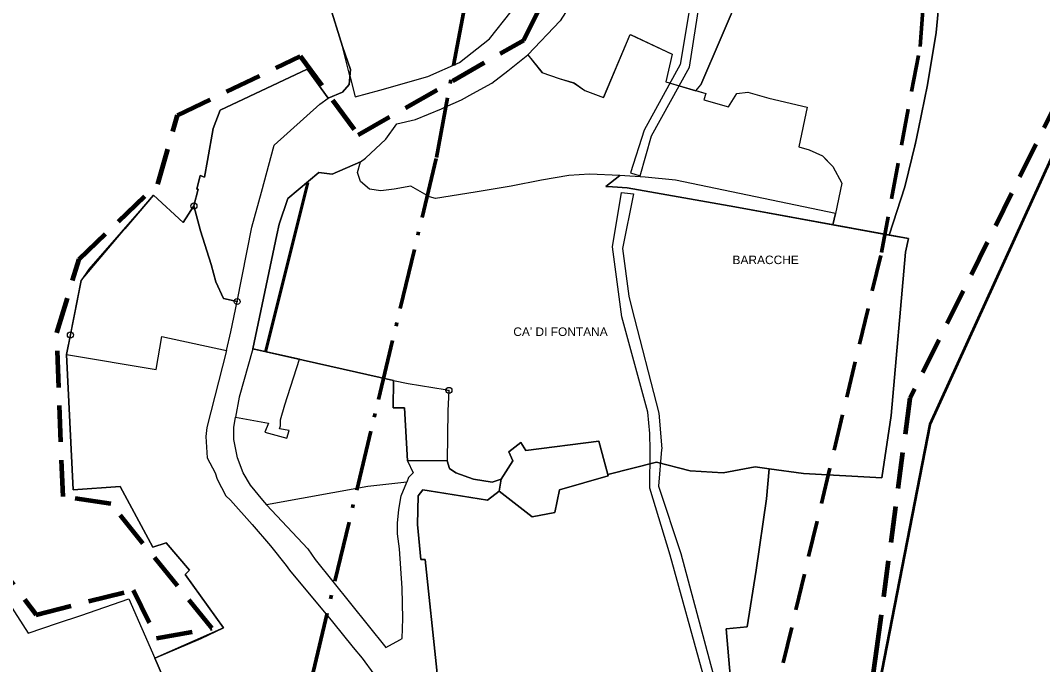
# Model space of a CAD drawing. Extents: x 654952 to 658955, y 890426 to 894481.
# Drawn here: x 657975.8 to 658312.8, y 893012.3 to 893224.6 of the extents above; entities that cross this region are included whole.
import ezdxf

# ---------------------------------------------------------------- set-up
doc = ezdxf.new("R2010")
doc.units = 0
doc.header["$LTSCALE"] = 4
doc.header["$PDMODE"] = 32
doc.header["$PDSIZE"] = 2
doc.linetypes.add('DOT_DASHED', pattern=[7.7, 5, -1.2, 0.3, -1.2])
doc.linetypes.add('MEDIUM_DASHED', pattern=[4.5, 3, -1.5])
for name, color, linetype, lineweight in [('1', 7, 'Continuous', 25), ('11', 7, 'Continuous', 25), ('14', 7, 'Continuous', 25), ('21', 7, 'Continuous', 25), ('22', 7, 'Continuous', 25), ('29', 7, 'Continuous', 25), ('31', 7, 'Continuous', 25), ('35', 7, 'Continuous', 25), ('40', 7, 'Continuous', 60), ('43', 7, 'Continuous', 25), ('45', 7, 'Continuous', 25), ('55', 7, 'Continuous', 25), ('57', 7, 'Continuous', 25), ('59', 7, 'Continuous', 53), ('7', 7, 'MEDIUM_DASHED', 100), ('9', 7, 'Continuous', 25)]:
    doc.layers.add(name, color=color, linetype=linetype, lineweight=lineweight)
doc.layers.add('58', color=7, linetype='Continuous')

msp = doc.modelspace()

# ---------------------------------------------------------------- linework, layer by layer
at = {"layer": '1'}
for points in [[(658047.87, 893100.44), (658046.72, 893093.87), (658057.53, 893091.84), (658056.37, 893088.94), (658063.63, 893086.94), (658064.37, 893089.44), (658061.25, 893089.94), (658061.5, 893090.94), (658061.5, 893092.94), (658063, 893097.94), (658067.75, 893112.94), (658052.43, 893116.4)], [(658166.5, 893085.94), (658142.46, 893082.84), (658140.75, 893085.44), (658136.87, 893082.44), (658138.13, 893079.44), (658134.25, 893073.44), (658133.63, 893069.44), (658144.5, 893060.94), (658152, 893062.44), (658153.5, 893069.94), (658169.53, 893074.45)]]:
    msp.add_lwpolyline(points, close=True, dxfattribs=at)
at = {"layer": '11'}
msp.add_line((658019.63, 893167.01), (658010.25, 893155.94), dxfattribs=at)
for points in [[(658035.13, 893155.19), (658033, 893163.44), (658029.5, 893157.94), (658019.63, 893167.01)], [(658010.25, 893155.94), (657998.39, 893142.55), (657995.81, 893138.9), (657991, 893114.44), (658020.52, 893109.58), (658022.37, 893120.44), (658043.72, 893115.82), (658045.13, 893121.94), (658047.25, 893131.94), (658042.75, 893132.94), (658040.25, 893138.44), (658038.63, 893144.19), (658035.13, 893155.19)]]:
    msp.add_lwpolyline(points, dxfattribs=at)
at = {"layer": '14'}
msp.add_lwpolyline([(658057.04, 893064.97), (658055.75, 893066.44), (658051.63, 893071.44), (658049.25, 893075.44), (658047.37, 893080.44), (658046.13, 893086.44), (658046.13, 893090.44), (658046.72, 893093.87), (658057.53, 893091.84), (658056.37, 893088.94), (658063.63, 893086.94), (658064.37, 893089.44), (658061.25, 893089.94), (658061.5, 893090.94), (658061.5, 893092.94), (658063, 893097.94), (658067.75, 893112.94), (658098.75, 893105.94), (658098.63, 893096.94), (658102.46, 893096.94), (658103.37, 893079.44), (658105.25, 893075.44), (658103.75, 893073.94), (658103.15, 893072.43), (658090.37, 893070.94), (658056.87, 893064.94)], close=True, dxfattribs=at)
at = {"layer": '21'}
msp.add_line((658143.12, 893213.23), (658147.75, 893207.44), dxfattribs=at)
for points in [[(658168.08, 893199.13), (658176.87, 893219.94), (658190.63, 893213.44), (658188.55, 893204.35), (658201.75, 893200.44), (658201.13, 893198.44)], [(658106, 893191.94), (658114.63, 893195.44), (658115.75, 893195.94), (658121.25, 893198.44), (658125, 893200.44), (658131.25, 893203.94), (658136.5, 893207.94), (658143.12, 893213.23)], [(658147.75, 893207.44), (658153.37, 893205.44), (658158.37, 893203.94), (658161.87, 893201.44), (658168.08, 893199.13)], [(658201.13, 893198.44), (658209.27, 893196.08), (658212, 893200.44), (658215.63, 893200.94), (658222.5, 893198.94), (658235.13, 893195.94), (658232.37, 893182.94), (658235.87, 893181.94), (658240.25, 893179.94), (658241.7, 893178.44), (658243.63, 893176.44), (658246.63, 893170.94), (658244.47, 893160.98), (658191.75, 893171.94)], [(658104.5, 893169.94), (658099, 893168.94), (658094.63, 893168.44), (658090.87, 893168.94), (658087.87, 893171.44), (658086.87, 893174.44), (658087.87, 893177.94), (658089.52, 893179.19), (658096.25, 893185.44), (658099.87, 893190.44), (658106, 893191.94)], [(658191.75, 893171.94), (658181.75, 893172.94), (658173.37, 893173.44), (658163.37, 893173.94), (658156.63, 893173.44), (658147.63, 893171.94), (658137.63, 893169.94), (658125.75, 893167.94), (658112.63, 893165.94), (658110.63, 893166.44), (658104.5, 893169.94)]]:
    msp.add_lwpolyline(points, dxfattribs=at)
at = {"layer": '22'}
for p, q in [((658173.39, 893173.42), (658168.76, 893169.8)), ((658244.47, 893160.98), (658191.75, 893171.94))]:
    msp.add_line(p, q, dxfattribs=at)
for points in [[(658104.5, 893169.94), (658099, 893168.94), (658094.63, 893168.44), (658090.87, 893168.94), (658087.87, 893171.44), (658086.87, 893174.44), (658087.87, 893177.94), (658078.61, 893173.94), (658074.13, 893174.44), (658064, 893165.94), (658061.13, 893157.44), (658060.37, 893153.94), (658052.43, 893116.4), (658098.75, 893105.94), (658103.63, 893104.94), (658115.87, 893102.94), (658117.05, 893102.64)], [(658173.37, 893173.44), (658163.37, 893173.94), (658156.63, 893173.44), (658147.63, 893171.94), (658137.63, 893169.94), (658125.75, 893167.94), (658112.63, 893165.94), (658110.63, 893166.44), (658104.5, 893169.94)], [(658168.76, 893169.8), (658173.39, 893173.42), (658173.37, 893173.44)], [(658191.75, 893171.94), (658181.75, 893172.94), (658173.39, 893173.44)], [(658222.69, 893076.77), (658233.93, 893075.3), (658259.82, 893073.82), (658262.84, 893094.33), (658267.64, 893148.16), (658268.57, 893152.66), (658211.31, 893163.16), (658175.87, 893169.44), (658170.94, 893169.69), (658168.76, 893169.8)], [(658168.76, 893169.8), (658170.94, 893169.69), (658175.87, 893169.44), (658211.31, 893163.16)], [(658211.31, 893163.16), (658243.66, 893157.23), (658244.46, 893160.98)], [(658117.05, 893102.64), (658116.75, 893095.94), (658116.5, 893079.44), (658117.25, 893076.94), (658119.37, 893075.44), (658125.13, 893073.44), (658131.37, 893072.44), (658134.25, 893073.44), (658138.13, 893079.44), (658136.87, 893082.44), (658140.75, 893085.44), (658142.46, 893082.84), (658166.5, 893085.94), (658169.41, 893074.9)], [(658169.41, 893074.9), (658185.51, 893078.96), (658196.6, 893076.12), (658207.53, 893075.52), (658218.01, 893077.46), (658222.69, 893076.77)]]:
    msp.add_lwpolyline(points, dxfattribs=at)
msp.add_point((658117.05, 893102.64), dxfattribs=at)
at = {"layer": '29'}
for points in [[(658222.69, 893076.77), (658218.01, 893077.46), (658207.53, 893075.52), (658196.6, 893076.12), (658185.51, 893078.96), (658169.41, 893074.9), (658169.53, 893074.45), (658153.5, 893069.94), (658152, 893062.44), (658144.5, 893060.94), (658133.63, 893069.44), (658129.75, 893066.44), (658108.5, 893069.94), (658106.87, 893067.94), (658106.75, 893058.44), (658107.75, 893046.94), (658109.25, 893046.94), (658113.13, 893010.44), (658113, 893006.44)], [(658203.13, 892991.94), (658208.87, 892998.44), (658210.87, 893004.69), (658209.9, 893007.55), (658208.52, 893024.05), (658215.39, 893024.69), (658218.4, 893043.42), (658221.75, 893066.94), (658222.69, 893076.77)]]:
    msp.add_lwpolyline(points, dxfattribs=at)
at = {"layer": '31'}
for points in [[(657992.28, 893120.92), (657992.28, 893120.93), (657995.81, 893138.9), (658010.25, 893155.94), (658019.63, 893167.01), (658029.5, 893157.94), (658033, 893163.44), (658034.37, 893168.94), (658034, 893168.94), (658035, 893173.44), (658036.5, 893172.94), (658037.49, 893178.44), (658039.37, 893188.94), (658041.63, 893194.94), (658070.34, 893208.51), (658077.25, 893198.94), (658082, 893200.94), (658084.13, 893203.44), (658084.63, 893208.44), (658082, 893215.94), (658077.5, 893230.44)], [(657993.13, 893069.94), (657991, 893114.44), (657992.28, 893120.92)], [(657964, 893044.94), (657978.35, 893022.67), (657988, 893025.94), (657995.75, 893028.44), (658011.5, 893033.94), (658020.13, 893014.44), (658035.37, 893020.94), (658042.8, 893024.46), (658030.13, 893041.94), (658031.5, 893043.44), (658023.87, 893052.44), (658019.5, 893050.94), (658008.63, 893070.94), (657993.13, 893069.94)]]:
    msp.add_lwpolyline(points, dxfattribs=at)
msp.add_point((657992.28, 893120.92), dxfattribs=at)
at = {"layer": '35'}
for points in [[(658163.63, 893487.74), (658169.21, 893467.42), (658166.2, 893457.42), (658156, 893428.28), (658153.22, 893422.3), (658135.37, 893392.24), (658124.56, 893374.75), (658116.74, 893358.02), (658113.17, 893337.22), (658113.97, 893295.43), (658113.18, 893282.04), (658111.83, 893275.53), (658108.79, 893265.05), (658105.79, 893258.24), (658105.21, 893257.43), (658101.06, 893253.7), (658099.39, 893252.75), (658072.01, 893242.12), (658074.5, 893234.44), (658077.5, 893230.44), (658082, 893215.94), (658084.63, 893208.44), (658084.42, 893206.29), (658086.13, 893199.43)], [(658086.13, 893199.43), (658094.34, 893201.54), (658110.1, 893206.14), (658120.59, 893210.69), (658130.42, 893218.53), (658137.61, 893227.46)]]:
    msp.add_lwpolyline(points, dxfattribs=at)
msp.add_lwpolyline([(658082, 893215.94), (658084.63, 893208.44), (658084.42, 893206.29)], close=True, dxfattribs=at)
at = {"layer": '40'}
msp.add_line((658070.57, 893171.13), (658056.6, 893115.21), dxfattribs=at)
at = {"layer": '43'}
for p, q in [((658176.88, 893219.95), (658190.63, 893213.45)), ((658190.63, 893213.45), (658188.56, 893204.36)), ((658147.75, 893207.44), (658153.37, 893205.44)), ((658188.55, 893204.35), (658198.48, 893201.41))]:
    msp.add_line(p, q, dxfattribs=at)
for points in [[(658194.44, 892991.44), (658195.63, 892939.94), (658197.42, 892935.77), (658200.61, 892919.2), (658240.85, 892913.21), (658275.65, 893091.39), (658324.67, 893198.8), (658324.98, 893205.94), (658316.81, 893217.01), (658315.67, 893225.5), (658324.05, 893218.98), (658327.46, 893312.74), (658329.63, 893434.42)], [(658222.58, 893266.06), (658222.07, 893266.04), (658209.24, 893263.92), (658170.14, 893265.17), (658170.14, 893265.17), (658167.76, 893254.43), (658164.28, 893244.53), (658160.18, 893234.63), (658153.76, 893224.46), (658143.12, 893213.23), (658147.76, 893207.45)], [(658198.48, 893201.41), (658200.15, 893203.39), (658213.49, 893234.6), (658222.58, 893266.04)], [(658271.84, 893188.89), (658274.85, 893203.3), (658277.65, 893220.56), (658279.85, 893243.85), (658280.46, 893265.84), (658237.96, 893264.45)], [(658280.46, 893265.84), (658279.85, 893243.85), (658277.65, 893220.56), (658274.85, 893203.3), (658271.84, 893188.89)], [(658213.49, 893234.6), (658200.15, 893203.39), (658198.48, 893201.42), (658201.75, 893200.44), (658201.13, 893198.45)], [(658161.87, 893201.44), (658168.08, 893199.13), (658168.15, 893199.29), (658176.87, 893219.94)], [(658153.37, 893205.44), (658158.38, 893203.95), (658161.88, 893201.45)], [(658201.13, 893198.45), (658209.28, 893196.09), (658212.01, 893200.45), (658215.63, 893200.95)], [(658215.63, 893200.95), (658222.5, 893198.94), (658235.12, 893195.94), (658232.38, 893182.95)], [(658271.84, 893188.89), (658270.86, 893184.17), (658267.36, 893169.74), (658262.26, 893153.82), (658268.57, 893152.66)], [(658262.26, 893153.82), (658267.36, 893169.74), (658270.86, 893184.17), (658271.83, 893188.84), (658271.84, 893188.89)], [(658232.38, 893182.95), (658235.87, 893181.94), (658240.25, 893179.94), (658243.63, 893176.45)], [(658243.63, 893176.45), (658246.63, 893170.95), (658244.47, 893160.98), (658243.66, 893157.23), (658262.26, 893153.82)], [(658268.57, 893152.66), (658268.57, 893152.66), (658267.64, 893148.16), (658262.84, 893094.33), (658259.82, 893073.82), (658233.93, 893075.3), (658222.69, 893076.77), (658221.75, 893066.94), (658218.4, 893043.42), (658215.39, 893024.69), (658208.52, 893024.05), (658209.9, 893007.55), (658210.87, 893004.69), (658208.87, 892998.44), (658203.13, 892991.94), (658194.44, 892991.44)]]:
    msp.add_lwpolyline(points, dxfattribs=at)
at = {"layer": '45', "linetype": 'DOT_DASHED', "lineweight": 70}
msp.add_lwpolyline([(657888.75, 892244.36), (657949.53, 892498.78), (657993.28, 892680.38), (658112.95, 893179.41), (658123.49, 893235.71), (658127.84, 893290.79), (658125.12, 893359.25), (658122.7, 893382.9), (658114.35, 893470.93), (658113.32, 893505.97), (658113.89, 893537.78), (658115.35, 893563.44), (658117.94, 893594.58), (658121.29, 893618.7), (658125.97, 893646.13), (658131.56, 893672.78), (658136.29, 893692.48), (658143.9, 893719.95), (658153.86, 893751.08), (658170.87, 893795.19), (658185.72, 893828.64), (658194.88, 893846.97), (658209.57, 893874.93), (658233.56, 893914.96)], dxfattribs=at)
at = {"layer": '45', "linetype": 'MEDIUM_DASHED', "lineweight": 70}
msp.add_lwpolyline([(658035.6, 892213.52), (658095.39, 892463.77), (658139.14, 892645.31), (658259.68, 893148.09), (658272.39, 893215.94), (658278.08, 893287.85), (658274.82, 893369.87), (658271.98, 893397.63), (658264.14, 893480.23), (658263.35, 893506.84), (658263.8, 893532.17), (658264.99, 893552.95), (658267.07, 893578), (658269.55, 893595.75), (658273.36, 893618.11), (658277.93, 893639.87), (658281.55, 893654.95), (658287.66, 893677.05), (658295.4, 893701.19), (658309.47, 893737.74), (658321.42, 893764.63), (658328.38, 893778.55), (658340.4, 893801.43), (658362.23, 893837.86)], dxfattribs=at)
at = {"layer": '55'}
for points in [[(658040.09, 892492.62), (658056.01, 892512.42), (658077.73, 892541.6), (658117.44, 892608.97), (658146.29, 892663.3), (658176.86, 892798.67), (658197.47, 892851.1), (658213.6, 892873.76), (658238.11, 892899.22), (658275.65, 893091.38), (658324.67, 893198.8), (658324.98, 893205.94), (658316.81, 893217.01), (658315.67, 893225.5), (658324.05, 893218.98), (658327.46, 893312.74), (658329.63, 893434.42), (658329.32, 893488.12), (658323.74, 893553.3), (658322.5, 893619.12), (658343.9, 893727.46), (658358.49, 893763.16), (658400.68, 893840.75), (658381.79, 893852.16)], [(658198.48, 893201.41), (658200.15, 893203.39), (658213.49, 893234.6), (658222.58, 893266.04), (658223.87, 893284.97), (658224.78, 893303.49), (658226.74, 893337.73), (658226.79, 893337.79), (658228.2, 893361.92), (658232, 893363.42), (658235.5, 893367.42), (658238.25, 893372.92), (658244, 893374.92), (658244.15, 893374.66), (658244.15, 893375.02), (658244.02, 893378.52), (658239.72, 893384.12)], [(658280.46, 893265.84), (658279.85, 893243.85), (658277.65, 893220.56), (658274.85, 893203.3), (658271.84, 893188.89), (658271.83, 893188.84)], [(658077.5, 893230.44), (658082, 893215.94), (658084.63, 893208.44), (658084.13, 893203.44), (658082, 893200.94), (658077.25, 893198.94), (658070.34, 893208.51), (658041.63, 893194.94), (658039.37, 893188.94), (658037.49, 893178.44), (658036.5, 893172.94), (658035, 893173.44), (658034, 893168.94), (658034.37, 893168.94), (658033, 893163.44), (658029.5, 893157.94), (658019.63, 893167.01), (657998.39, 893142.55), (657995.81, 893138.9), (657991, 893114.44), (657993.13, 893069.94)], [(658147.75, 893207.44), (658153.37, 893205.44), (658158.37, 893203.94), (658161.87, 893201.44), (658168.08, 893199.13), (658168.15, 893199.29), (658176.87, 893219.94)], [(658176.87, 893219.94), (658190.63, 893213.44), (658188.55, 893204.35), (658198.48, 893201.41)], [(658106, 893191.94), (658114.63, 893195.44), (658115.75, 893195.94), (658121.25, 893198.44), (658125, 893200.44), (658131.25, 893203.94), (658136.5, 893207.94), (658143.12, 893213.23), (658147.75, 893207.44)], [(658114.73, 893068.91), (658129.75, 893066.44), (658133.63, 893069.44), (658134.25, 893073.44), (658131.37, 893072.44), (658125.13, 893073.44), (658119.37, 893075.44), (658117.25, 893076.94), (658116.5, 893079.44), (658103.37, 893079.44), (658102.46, 893096.94), (658098.63, 893096.94), (658098.75, 893105.94), (658052.43, 893116.4), (658060.37, 893153.94), (658061.13, 893157.44), (658064, 893165.94), (658074.13, 893174.44), (658078.61, 893173.94), (658087.87, 893177.94), (658089.52, 893179.19), (658096.25, 893185.44), (658099.87, 893190.44), (658106, 893191.94)], [(658271.83, 893188.84), (658267.36, 893169.74), (658262.26, 893153.82), (658268.57, 893152.66), (658267.64, 893148.16), (658262.84, 893094.33), (658259.82, 893073.82), (658235.69, 893075.2)], [(658235.69, 893075.2), (658233.93, 893075.3), (658222.69, 893076.77), (658221.75, 893066.94)], [(657993.13, 893069.94), (658008.63, 893070.94), (658019.5, 893050.94), (658023.87, 893052.44), (658031.5, 893043.44), (658030.13, 893041.94), (658042.8, 893024.46), (658020.13, 893014.44), (658028.37, 892995.44), (658036, 892977.94), (658032, 892974.94), (658032, 892939.44), (658027.1, 892926.19), (658004.83, 892883.1), (657992.56, 892863.36), (657978.36, 892837.99), (657946.04, 892783.96)], [(658113, 893006.44), (658113.13, 893010.44), (658109.25, 893046.94), (658107.75, 893046.94), (658106.75, 893058.44), (658106.87, 893067.94), (658108.5, 893069.94), (658114.73, 893068.91)], [(658221.75, 893066.94), (658218.4, 893043.42), (658215.39, 893024.69)], [(658215.39, 893024.69), (658208.52, 893024.05), (658209.9, 893007.55), (658210.87, 893004.69), (658208.87, 892998.44), (658203.13, 892991.94), (658194.44, 892991.44), (658195.29, 892954.75)]]:
    msp.add_lwpolyline(points, dxfattribs=at)
at = {"layer": '57'}
msp.add_lwpolyline([(658180.08, 893173.37), (658183.87, 893186.5), (658196.37, 893209.19), (658201.62, 893243.06), (658198.93, 893243.63), (658193.31, 893210), (658181.43, 893188.37), (658176.95, 893174.37)], close=True, dxfattribs=at)
for points in [[(658138.93, 892834.25), (658145.93, 892850.5), (658152.37, 892860.75), (658177.62, 892889.06), (658198.37, 892925.87), (658201.24, 892933.19), (658201.99, 892940.5), (658202.99, 892966.81), (658207.68, 892995), (658200.93, 893009.06), (658190.05, 893048.37), (658183.31, 893070.44), (658183.43, 893082.94), (658183.31, 893088.5), (658182.62, 893095.44), (658174.12, 893126.94), (658170.99, 893149.94), (658173.93, 893167.87), (658177.87, 893167.44)], [(658177.87, 893167.44), (658174.31, 893149.44), (658176.43, 893133.75), (658177.37, 893129.63), (658186.31, 893095.13), (658187.24, 893083.44), (658187.18, 893083.19), (658186.18, 893071.13), (658193.49, 893048.94), (658204.12, 893009.56), (658210.74, 892994.94), (658205.87, 892967.31), (658204.43, 892940.44), (658204.05, 892932.94), (658201.74, 892925.63), (658194.81, 892913.63), (658188.93, 892902.87), (658182.18, 892887.87), (658155.81, 892857.19), (658141.87, 892833.69), (658138.93, 892834.25)]]:
    msp.add_lwpolyline(points, dxfattribs=at)
at = {"layer": '59'}
msp.add_lwpolyline([(658343.9, 893727.46), (658322.5, 893619.12), (658323.74, 893553.3), (658329.32, 893488.12), (658329.63, 893434.42), (658327.46, 893312.74), (658324.05, 893218.98), (658315.67, 893225.5), (658316.81, 893217.01), (658324.98, 893205.94), (658324.67, 893198.8), (658275.65, 893091.38), (658238.11, 892899.22), (658213.6, 892873.76), (658197.47, 892851.1), (658176.86, 892798.67), (658146.29, 892663.3), (658117.44, 892608.97), (658077.73, 892541.6), (658056.01, 892512.42), (658015.06, 892461.51), (657983.11, 892330.2)], dxfattribs=at)
at = {"layer": '7'}
for points in [[(658345.21, 893730.15), (658324.56, 893626.35), (658326.18, 893565.54), (658329.82, 893531.88), (658330.62, 893468.63), (658337.11, 893409.83), (658336.7, 893350.23), (658336.29, 893306.44), (658326.56, 893216.03), (658269.02, 893100.07), (658258.05, 893017.47), (658246.92, 892936.53), (658240.25, 892915.99), (658214.74, 892887.33), (658197.25, 892862.68), (658171.38, 892793.94), (658146.27, 892665.82), (658107.77, 892604.19), (658053.07, 892513.78), (658011.87, 892462.81), (657985.13, 892331.98)], [(657966.34, 893048.2), (657980.93, 893028.74), (658012.94, 893036.85), (658020.64, 893021.04), (658038.87, 893024.28), (658005.65, 893065.23), (657989.84, 893067.67), (657987.82, 893121.59), (657995.11, 893145.92), (658021.05, 893170.65), (658027.53, 893193.35), (658068.06, 893212.81), (658087.1, 893186.86), (658141.8, 893218.08), (658164.49, 893263.9)]]:
    msp.add_lwpolyline(points, dxfattribs=at)
at = {"layer": '9'}
msp.add_line((658033, 893163.44), (658035.13, 893155.19), dxfattribs=at)
for points in [[(658047.25, 893131.94), (658052.13, 893156.44), (658055.25, 893167.94), (658059.5, 893183.44), (658074.5, 893196.94), (658077.25, 893198.94), (658070.34, 893208.51), (658041.63, 893194.94), (658039.37, 893188.94), (658037.49, 893178.44), (658036.5, 893172.94), (658035, 893173.44), (658034, 893168.94), (658034.37, 893168.94), (658033, 893163.44)], [(658035.13, 893155.19), (658038.63, 893144.19), (658040.25, 893138.44), (658042.75, 893132.94), (658047.25, 893131.94)], [(658028.37, 892995.44), (658020.13, 893014.44), (658035.37, 893020.94), (658042.8, 893024.46), (658030.13, 893041.94), (658031.5, 893043.44), (658023.87, 893052.44), (658019.5, 893050.94), (658008.63, 893070.94), (657993.13, 893069.94), (657991, 893114.44), (658020.52, 893109.58), (658022.37, 893120.44), (658043.72, 893115.82), (658037.25, 893090.44), (658036.87, 893087.44), (658037.37, 893080.44), (658040, 893075.44), (658040.63, 893073.44), (658043.5, 893067.94), (658045, 893066.44), (658052.25, 893058.44), (658058.25, 893051.44), (658063.37, 893044.94), (658064.5, 893043.44), (658078.63, 893026.44), (658085.5, 893017.94)], [(658098.63, 893096.94), (658098.75, 893105.94), (658103.63, 893104.94)], [(658103.63, 893104.94), (658115.87, 893102.94), (658117.05, 893102.64), (658116.75, 893095.94), (658116.5, 893079.44), (658112.63, 893079.44), (658103.37, 893079.44), (658102.46, 893096.94), (658098.63, 893096.94)], [(658090.37, 893070.94), (658056.87, 893064.94), (658070.5, 893050.44), (658073, 893046.94), (658096.25, 893017.94), (658100.87, 893020.44)], [(658100.13, 893055.44), (658100.13, 893058.94), (658100.5, 893063.44), (658101.37, 893067.94), (658103.15, 893072.43), (658090.37, 893070.94)], [(658100.87, 893020.44), (658101.63, 893020.94), (658101.87, 893027.44), (658101.63, 893037.44), (658100.75, 893050.44), (658100.13, 893055.44)], [(657964, 893044.94), (657978.35, 893022.67), (657988, 893025.94), (657995.75, 893028.44), (658011.5, 893033.94), (658020.13, 893014.44), (658028.37, 892995.44), (658036, 892977.94), (658032, 892974.94), (658032, 892939.44), (658027.1, 892926.19), (658024.63, 892929.44), (658019.5, 892936.44), (658013.87, 892943.94), (658005.5, 892954.94), (658001.25, 892960.44), (657998.25, 892963.44), (657989.5, 892974.44), (657987.37, 892977.44), (657985.63, 892979.44), (657981, 892984.44), (657973.25, 892994.44)], [(658085.5, 893017.94), (658088.5, 893014.44), (658092.31, 893009.19), (658092.31, 893009.19), (658092.31, 893009.19), (658092.31, 893009.19)]]:
    msp.add_lwpolyline(points, dxfattribs=at)
msp.add_lwpolyline([(658035.13, 893155.19), (658038.63, 893144.19), (658040.25, 893138.44), (658042.75, 893132.94), (658047.25, 893131.94), (658052.13, 893156.44), (658055.25, 893167.94), (658059.5, 893183.44), (658074.5, 893196.94), (658077.25, 893198.94), (658070.34, 893208.51), (658041.63, 893194.94), (658039.37, 893188.94), (658037.49, 893178.44), (658036.5, 893172.94), (658035, 893173.44), (658034, 893168.94), (658034.37, 893168.94), (658033, 893163.44)], close=True, dxfattribs=at)
for p in [(658033, 893163.44), (658047.25, 893131.94)]:
    msp.add_point(p, dxfattribs=at)

# ---------------------------------------------------------------- texts
at = {"layer": '58', "width": 1.05}
for s, p in [('BARACCHE', (658210.56, 893144.27)), ("CA' DI FONTANA", (658138.29, 893120.59))]:
    msp.add_text(s, height=2.801, dxfattribs=at).set_placement(p)

doc.saveas('drawing.dxf')
